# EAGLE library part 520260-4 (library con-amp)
AMP connector
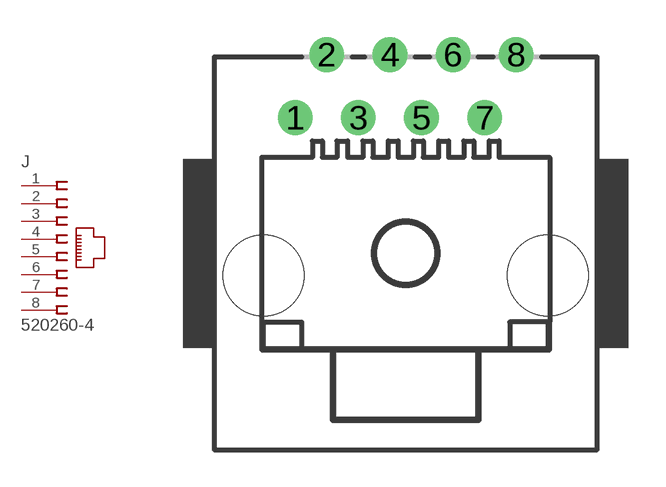
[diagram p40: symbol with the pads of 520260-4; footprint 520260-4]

Designator prefix J

## 520260-4 (MF: TYCO ELECTRONICS; MPN: 5520260-4; OC_FARNELL: 1557666; OC_NEWARK: 42K7229)  [520260-4]
1  1  pas
2  2  pas
3  3  pas
4  4  pas
5  5  pas
6  6  pas
7  7  pas
8  8  pas

## Footprint 520260-4 (pad centres in mm)
Modular Jack Keyed with Panel Stops
drill 0.889 round: 1 -4.445,5.461; 2 -3.175,8.001; 3 -1.905,5.461; 4 -0.635,8.001; 5 0.635,5.461; 6 1.905,8.001; 7 3.175,5.461; 8 4.445,8.001
hole 3.251 at -5.715,-0.889
hole 3.251 at 5.715,-0.889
